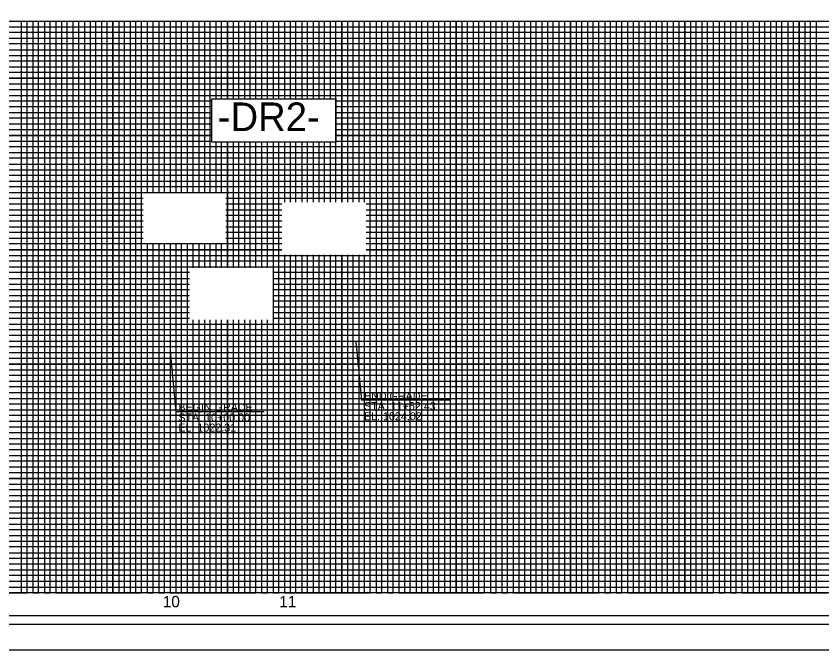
# Model space of a CAD drawing. Extents: x 1427348 to 1429459, y 856278 to 857378.
# Drawn here: x 1428179 to 1428884, y 856278 to 856832 of the extents above; entities that cross this region are included whole.
import ezdxf

# ---------------------------------------------------------------- set-up
doc = ezdxf.new("R2010")
doc.units = 0
for name, color, linetype in [('Exist Vertical Profile Horizontal Axis Label Major', 7, 'Continuous'), ('Prop Grid Mask', 7, 'Continuous'), ('Prop Vertical Profile Curve Label', 7, 'Continuous'), ('Prop VPI Label', 7, 'Continuous'), ('Sheet Cutting Line CELL', 7, 'Continuous'), ('Sheet DOT Grid CELL', 7, 'Continuous'), ('Sheet Layout Profile Border Port 2', 7, 'Continuous'), ('Sheet Plot Border Inside CELL', 7, 'Continuous'), ('Sheet Plot Border Outside CELL', 7, 'Continuous'), ('Sheet Profile CELL', 7, 'Continuous'), ('Sheet Profile Grid Major CELL', 7, 'Continuous'), ('Sheet Profile Grid Middle CELL', 7, 'Continuous'), ('Sheet Profile Grid Minor CELL', 7, 'Continuous')]:
    doc.layers.add(name, color=color, linetype=linetype)

msp = doc.modelspace()

# ---------------------------------------------------------------- linework, layer by layer
at = {"layer": 'Prop Grid Mask'}
msp.add_lwpolyline([(1428350.45, 856759.7), (1428458.77, 856759.7), (1428458.77, 856721.66), (1428350.45, 856721.66)], close=True, dxfattribs=at)
at = {"layer": 'Prop VPI Label'}
for p, q in [((1428476.42, 856547.42), (1428481.19, 856495.88)), ((1428313.99, 856538.89), (1428318.84, 856485.93)), ((1428558.65, 856495.88), (1428481.19, 856495.88)), ((1428396.3, 856485.93), (1428318.84, 856485.93))]:
    msp.add_line(p, q, dxfattribs=at)
at = {"layer": 'Sheet Cutting Line CELL'}
msp.add_line((1427596.99, 856277.58), (1429280.99, 856277.58), dxfattribs=at)
at = {"layer": 'Sheet DOT Grid CELL'}
for p, q in [((1427763.99, 856827.58), (1429263.88, 856827.58)), ((1428213.99, 856827.58), (1428213.99, 856327.58)), ((1428263.99, 856827.58), (1428263.99, 856327.58)), ((1428313.99, 856827.58), (1428313.99, 856677.37)), ((1428363.99, 856827.58), (1428363.99, 856759.7)), ((1428413.99, 856827.58), (1428413.99, 856759.7)), ((1428463.99, 856827.58), (1428463.99, 856669.07)), ((1428513.99, 856827.58), (1428513.99, 856327.58)), ((1428563.99, 856827.58), (1428563.99, 856327.58)), ((1428613.99, 856827.58), (1428613.99, 856327.58)), ((1428663.99, 856827.58), (1428663.99, 856327.58)), ((1428713.99, 856827.58), (1428713.99, 856327.58)), ((1428763.99, 856827.58), (1428763.99, 856327.58)), ((1428813.99, 856827.58), (1428813.99, 856327.58)), ((1428863.99, 856827.58), (1428863.99, 856327.58)), ((1427763.99, 856777.58), (1429263.88, 856777.58)), ((1428009.5, 856727.58), (1428350.45, 856727.58)), ((1428458.77, 856727.58), (1429263.88, 856727.58)), ((1428363.99, 856721.66), (1428363.99, 856611.64)), ((1428413.99, 856721.66), (1428413.99, 856669.07)), ((1428023.59, 856677.58), (1429263.88, 856677.58)), ((1428313.99, 856633.02), (1428313.99, 856327.58)), ((1427763.99, 856627.58), (1428411.65, 856627.58)), ((1428485.43, 856627.58), (1429263.88, 856627.58)), ((1428413.99, 856623.03), (1428413.99, 856327.58)), ((1428463.99, 856623.03), (1428463.99, 856327.58)), ((1427763.99, 856577.58), (1428330.81, 856577.58)), ((1428403.82, 856577.58), (1429263.88, 856577.58)), ((1428363.99, 856566.21), (1428363.99, 856327.58)), ((1427763.99, 856527.58), (1429263.88, 856527.58)), ((1427763.99, 856477.58), (1429263.88, 856477.58)), ((1427763.99, 856427.58), (1429263.88, 856427.58)), ((1427763.99, 856377.58), (1429263.88, 856377.58))]:
    msp.add_line(p, q, dxfattribs=at)
at = {"layer": 'Sheet Layout Profile Border Port 2'}
msp.add_lwpolyline([(1427813.99, 856827.58), (1429213.99, 856827.58), (1429213.99, 856327.58), (1427813.99, 856327.58)], close=True, dxfattribs=at)
at = {"layer": 'Sheet Plot Border Inside CELL'}
msp.add_line((1427609.99, 856300.03), (1429276.49, 856300.03), dxfattribs=at)
at = {"layer": 'Sheet Plot Border Outside CELL'}
msp.add_lwpolyline([(1427596.99, 856277.58), (1429280.99, 856277.58), (1429280.99, 857377.58), (1427596.99, 857377.58)], close=True, dxfattribs=at)
at = {"layer": 'Sheet Profile CELL'}
for p, q in [((1427763.99, 856827.58), (1429263.99, 856827.58)), ((1429263.99, 856327.58), (1427763.99, 856327.58)), ((1427763.99, 856307.58), (1429263.99, 856307.58))]:
    msp.add_line(p, q, dxfattribs=at)
msp.add_lwpolyline([(1429263.99, 857347.58), (1427763.99, 857347.58), (1427763.99, 856307.58), (1429263.99, 856307.58)], close=True, dxfattribs=at)
at = {"layer": 'Sheet Profile Grid Major CELL'}
for p, q in [((1428263.99, 856827.58), (1428313.99, 856827.58)), ((1428363.99, 856827.58), (1428413.99, 856827.58)), ((1428463.99, 856827.58), (1428513.99, 856827.58)), ((1428563.99, 856827.58), (1428613.99, 856827.58)), ((1428663.99, 856827.58), (1428713.99, 856827.58)), ((1428763.99, 856827.58), (1428813.99, 856827.58)), ((1428863.99, 856827.58), (1428913.99, 856827.58))]:
    msp.add_line(p, q, dxfattribs=at)
for points in [[(1428013.99, 856665.19), (1428013.99, 856327.58), (1428063.99, 856327.58), (1428063.99, 856827.58), (1428113.99, 856827.58), (1428113.99, 856327.58), (1428163.99, 856327.58), (1428163.99, 856827.58), (1428213.99, 856827.58), (1428213.99, 856327.58), (1428263.99, 856327.58), (1428263.99, 856827.58), (1428313.99, 856827.58), (1428313.99, 856677.37)], [(1428363.99, 856759.7), (1428363.99, 856827.58), (1428413.99, 856827.58), (1428413.99, 856759.7)], [(1428463.99, 856669.07), (1428463.99, 856827.58), (1428513.99, 856827.58), (1428513.99, 856327.58), (1428563.99, 856327.58), (1428563.99, 856827.58), (1428613.99, 856827.58), (1428613.99, 856327.58), (1428663.99, 856327.58), (1428663.99, 856827.58), (1428713.99, 856827.58), (1428713.99, 856327.58), (1428763.99, 856327.58), (1428763.99, 856827.58), (1428813.99, 856827.58), (1428813.99, 856327.58), (1428863.99, 856327.58), (1428863.99, 856827.58), (1428913.99, 856827.58)], [(1429263.99, 856777.58), (1427763.99, 856777.58)], [(1428350.45, 856727.58), (1428009.5, 856727.58)], [(1429263.99, 856727.58), (1428458.77, 856727.58)], [(1428363.99, 856611.64), (1428363.99, 856721.66)], [(1428413.99, 856721.66), (1428413.99, 856669.07)], [(1428023.59, 856677.58), (1429263.99, 856677.58)], [(1428313.99, 856633.02), (1428313.99, 856327.58), (1428363.99, 856327.58), (1428363.99, 856566.21)], [(1428411.65, 856627.58), (1427763.99, 856627.58), (1427763.99, 856577.58), (1428330.81, 856577.58)], [(1429263.99, 856627.58), (1428485.43, 856627.58)], [(1428413.99, 856623.03), (1428413.99, 856327.58), (1428463.99, 856327.58), (1428463.99, 856623.03)], [(1428403.82, 856577.58), (1429263.99, 856577.58)], [(1429263.99, 856527.58), (1427763.99, 856527.58), (1427763.99, 856477.58), (1429263.99, 856477.58)], [(1429263.99, 856427.58), (1427763.99, 856427.58), (1427763.99, 856427.58), (1427763.99, 856377.58), (1429263.99, 856377.58)], [(1429263.99, 856327.58), (1427763.99, 856327.58)]]:
    msp.add_lwpolyline(points, dxfattribs=at)
at = {"layer": 'Sheet Profile Grid Middle CELL'}
for points in [[(1427988.99, 856752.4), (1427988.99, 856827.58), (1428038.99, 856827.58), (1428038.99, 856327.58), (1428088.99, 856327.58), (1428088.99, 856827.58), (1428138.99, 856827.58), (1428138.99, 856327.58), (1428188.99, 856327.58), (1428188.99, 856827.58), (1428238.99, 856827.58), (1428238.99, 856327.58), (1428288.99, 856327.58), (1428288.99, 856827.58), (1428338.99, 856827.58), (1428338.99, 856677.37)], [(1428388.99, 856759.7), (1428388.99, 856827.58), (1428438.99, 856827.58), (1428438.99, 856759.7)], [(1428438.99, 856623.03), (1428438.99, 856327.58), (1428488.99, 856327.58), (1428488.99, 856827.58), (1428538.99, 856827.58), (1428538.99, 856327.58), (1428588.99, 856327.58), (1428588.99, 856827.58), (1428638.99, 856827.58), (1428638.99, 856327.58), (1428688.99, 856327.58), (1428688.99, 856827.58), (1428738.99, 856827.58), (1428738.99, 856327.58), (1428788.99, 856327.58), (1428788.99, 856827.58), (1428838.99, 856827.58), (1428838.99, 856327.58), (1428888.99, 856327.58)], [(1427763.99, 856802.58), (1429263.99, 856802.58)], [(1428350.45, 856752.58), (1427763.99, 856752.58), (1427763.99, 856702.58), (1427867.72, 856702.58)], [(1429263.99, 856752.58), (1428458.77, 856752.58)], [(1428388.99, 856611.64), (1428388.99, 856721.66)], [(1428438.99, 856721.66), (1428438.99, 856669.07)], [(1428023.59, 856702.58), (1429263.99, 856702.58)], [(1428290.23, 856652.58), (1427763.99, 856652.58), (1427763.99, 856602.58), (1428330.81, 856602.58)], [(1428411.65, 856652.58), (1428362.68, 856652.58)], [(1429263.99, 856652.58), (1428485.43, 856652.58)], [(1428338.99, 856633.02), (1428338.99, 856611.64)], [(1428403.82, 856602.58), (1429263.99, 856602.58)], [(1428338.99, 856566.21), (1428338.99, 856327.58), (1428388.99, 856327.58), (1428388.99, 856327.58), (1428388.99, 856566.21)], [(1429263.99, 856552.58), (1427763.99, 856552.58), (1427763.99, 856502.58), (1429263.99, 856502.58)], [(1429263.99, 856452.58), (1427763.99, 856452.58), (1427763.99, 856402.58), (1429263.99, 856402.58)], [(1429263.99, 856352.58), (1427763.99, 856352.58)]]:
    msp.add_lwpolyline(points, dxfattribs=at)
at = {"layer": 'Sheet Profile Grid Minor CELL'}
for p, q in [((1427813.99, 856822.58), (1429213.99, 856822.58)), ((1429213.99, 856817.58), (1427813.99, 856817.58)), ((1427813.99, 856812.58), (1429213.99, 856812.58)), ((1429213.99, 856807.58), (1427813.99, 856807.58)), ((1427813.99, 856797.58), (1429213.99, 856797.58)), ((1429213.99, 856792.58), (1427813.99, 856792.58)), ((1427813.99, 856787.58), (1429213.99, 856787.58)), ((1429213.99, 856782.58), (1427813.99, 856782.58)), ((1427813.99, 856772.58), (1429213.99, 856772.58)), ((1429213.99, 856767.58), (1427813.99, 856767.58)), ((1427813.99, 856762.58), (1429213.99, 856762.58)), ((1428350.45, 856757.58), (1427813.99, 856757.58)), ((1429213.99, 856757.58), (1428458.77, 856757.58)), ((1428009.5, 856747.58), (1428350.45, 856747.58)), ((1428458.77, 856747.58), (1429213.99, 856747.58)), ((1428350.45, 856742.58), (1428009.5, 856742.58)), ((1428009.5, 856737.58), (1428350.45, 856737.58)), ((1429213.99, 856742.58), (1428458.77, 856742.58)), ((1428458.77, 856737.58), (1429213.99, 856737.58)), ((1428350.45, 856732.58), (1428009.5, 856732.58)), ((1429213.99, 856732.58), (1428458.77, 856732.58)), ((1428009.5, 856722.58), (1428350.45, 856722.58)), ((1429213.99, 856717.58), (1428009.5, 856717.58)), ((1428458.77, 856722.58), (1429213.99, 856722.58)), ((1427813.99, 856712.58), (1429213.99, 856712.58)), ((1429213.99, 856707.58), (1428023.59, 856707.58)), ((1428023.59, 856697.58), (1429213.99, 856697.58)), ((1429213.99, 856692.58), (1428023.59, 856692.58)), ((1428023.59, 856687.58), (1429213.99, 856687.58)), ((1429213.99, 856682.58), (1428023.59, 856682.58)), ((1428023.59, 856672.58), (1428290.23, 856672.58)), ((1428290.23, 856667.58), (1428023.59, 856667.58)), ((1428362.68, 856672.58), (1429213.99, 856672.58)), ((1428411.65, 856667.58), (1428362.68, 856667.58)), ((1429213.99, 856667.58), (1428485.43, 856667.58)), ((1427813.99, 856662.58), (1428290.23, 856662.58)), ((1428362.68, 856662.58), (1428411.65, 856662.58)), ((1428485.43, 856662.58), (1429213.99, 856662.58)), ((1428290.23, 856657.58), (1427813.99, 856657.58)), ((1428411.65, 856657.58), (1428362.68, 856657.58)), ((1429213.99, 856657.58), (1428485.43, 856657.58)), ((1427813.99, 856647.58), (1428290.23, 856647.58)), ((1428362.68, 856647.58), (1428411.65, 856647.58)), ((1428485.43, 856647.58), (1429213.99, 856647.58)), ((1428290.23, 856642.58), (1427813.99, 856642.58)), ((1428411.65, 856642.58), (1428362.68, 856642.58)), ((1429213.99, 856642.58), (1428485.43, 856642.58)), ((1427813.99, 856637.58), (1428290.23, 856637.58)), ((1428411.65, 856632.67), (1427813.99, 856632.73)), ((1428362.68, 856637.58), (1428411.65, 856637.58)), ((1428485.43, 856637.58), (1429213.99, 856637.58)), ((1429213.99, 856632.58), (1428485.43, 856632.66)), ((1427813.99, 856622.58), (1429213.99, 856622.58)), ((1429213.99, 856617.58), (1427813.99, 856617.58)), ((1427813.99, 856612.58), (1429213.99, 856612.58)), ((1428330.81, 856607.58), (1427813.99, 856607.58)), ((1429213.99, 856607.58), (1428403.82, 856607.58)), ((1427813.99, 856597.58), (1428330.81, 856597.58)), ((1428403.82, 856597.58), (1429213.99, 856597.58)), ((1428330.81, 856592.58), (1427813.99, 856592.58)), ((1429213.99, 856592.58), (1428403.82, 856592.58)), ((1427813.99, 856587.58), (1428330.81, 856587.58)), ((1428330.81, 856582.58), (1427813.99, 856582.58)), ((1428403.82, 856587.58), (1429213.99, 856587.58)), ((1429213.99, 856582.58), (1428403.82, 856582.58)), ((1427813.99, 856572.58), (1428330.81, 856572.58)), ((1428403.82, 856572.58), (1429213.99, 856572.58)), ((1428330.81, 856567.58), (1427813.99, 856567.58)), ((1427813.99, 856562.58), (1429213.99, 856562.58)), ((1429213.99, 856567.58), (1428403.82, 856567.58)), ((1429213.99, 856557.58), (1427813.99, 856557.58)), ((1427813.99, 856547.58), (1429213.99, 856547.58)), ((1429213.99, 856542.58), (1427813.99, 856542.58)), ((1427813.99, 856537.58), (1429213.99, 856537.58)), ((1429213.99, 856532.58), (1427813.99, 856532.58)), ((1427813.99, 856522.58), (1429213.99, 856522.58)), ((1429213.99, 856517.58), (1427813.99, 856517.58)), ((1427813.99, 856512.58), (1429213.99, 856512.58)), ((1429213.99, 856507.58), (1427813.99, 856507.58)), ((1427813.99, 856497.58), (1429213.99, 856497.58)), ((1429213.99, 856492.58), (1427813.99, 856492.58)), ((1427813.99, 856487.58), (1429213.99, 856487.58)), ((1429213.99, 856482.58), (1427813.99, 856482.58)), ((1427813.99, 856472.58), (1429213.99, 856472.58)), ((1429213.99, 856467.58), (1427813.99, 856467.58)), ((1427813.99, 856462.58), (1429213.99, 856462.58)), ((1429213.99, 856457.58), (1427813.99, 856457.58)), ((1427813.99, 856447.58), (1429213.99, 856447.58)), ((1429213.99, 856442.58), (1427813.99, 856442.58)), ((1427813.99, 856437.58), (1429213.99, 856437.58)), ((1429213.99, 856432.58), (1427813.99, 856432.58)), ((1427813.99, 856422.58), (1429213.99, 856422.58)), ((1429213.99, 856417.58), (1427813.99, 856417.58)), ((1427813.99, 856412.58), (1429213.99, 856412.58)), ((1429213.99, 856407.58), (1427813.99, 856407.58)), ((1427813.99, 856397.58), (1429213.99, 856397.58)), ((1429213.99, 856392.58), (1427813.99, 856392.58)), ((1427813.99, 856387.58), (1429213.99, 856387.58)), ((1429213.99, 856382.58), (1427813.99, 856382.58)), ((1427813.99, 856372.58), (1429213.99, 856372.58)), ((1429213.99, 856367.58), (1427813.99, 856367.58)), ((1427813.99, 856362.58), (1429213.99, 856362.58)), ((1429213.99, 856357.58), (1427813.99, 856357.58)), ((1427813.99, 856347.58), (1429213.99, 856347.58)), ((1429213.99, 856342.58), (1427813.99, 856342.58)), ((1427813.99, 856337.58), (1429213.99, 856337.58)), ((1427813.99, 856332.58), (1429213.99, 856332.58))]:
    msp.add_line(p, q, dxfattribs=at)
for points in [[(1428178.99, 856327.58), (1428183.99, 856327.58), (1428183.99, 856827.58), (1428193.99, 856827.58), (1428193.99, 856327.58), (1428198.99, 856327.58), (1428198.99, 856827.58), (1428203.99, 856827.58), (1428203.99, 856327.58), (1428208.99, 856327.58), (1428208.99, 856827.58), (1428218.99, 856827.58), (1428218.99, 856327.58), (1428223.99, 856327.58), (1428223.99, 856827.58), (1428228.99, 856827.58), (1428228.99, 856327.58), (1428233.99, 856327.58), (1428233.99, 856827.58), (1428243.99, 856827.58), (1428243.99, 856327.58), (1428248.99, 856327.58), (1428248.99, 856827.58), (1428253.99, 856827.58), (1428253.99, 856327.58), (1428258.99, 856327.58), (1428258.99, 856827.58), (1428268.99, 856827.58), (1428268.99, 856327.58), (1428273.99, 856327.58), (1428273.99, 856827.58), (1428278.99, 856827.58), (1428278.99, 856327.58), (1428283.99, 856327.58), (1428283.99, 856827.58), (1428293.99, 856827.58), (1428293.99, 856677.37)], [(1428298.99, 856677.37), (1428298.99, 856827.58), (1428303.99, 856827.58), (1428303.99, 856677.37)], [(1428308.99, 856677.37), (1428308.99, 856827.58), (1428318.99, 856827.58), (1428318.99, 856677.37)], [(1428323.99, 856677.37), (1428323.99, 856827.58), (1428328.99, 856827.58), (1428328.99, 856677.37)], [(1428333.99, 856677.37), (1428333.99, 856827.58), (1428343.99, 856827.58)], [(1428343.99, 856827.58), (1428343.99, 856677.37)], [(1428348.99, 856677.37), (1428348.99, 856827.58), (1428353.99, 856827.58), (1428353.99, 856759.7)], [(1428358.99, 856759.7), (1428358.99, 856827.58), (1428368.99, 856827.58), (1428368.99, 856759.7)], [(1428373.99, 856759.7), (1428373.99, 856827.58), (1428378.99, 856827.58), (1428378.99, 856759.7)], [(1428383.99, 856759.7), (1428383.99, 856827.58), (1428393.99, 856827.58), (1428393.99, 856759.7)], [(1428398.99, 856759.7), (1428398.99, 856827.58), (1428403.99, 856827.58), (1428403.99, 856759.7)], [(1428408.99, 856759.7), (1428408.99, 856827.58), (1428418.99, 856827.58), (1428418.99, 856759.7)], [(1428423.99, 856759.7), (1428423.99, 856827.58), (1428428.99, 856827.58), (1428428.99, 856759.7)], [(1428433.99, 856759.7), (1428433.99, 856827.58), (1428443.99, 856827.58), (1428443.99, 856759.7)], [(1428448.99, 856759.7), (1428448.99, 856827.58), (1428453.99, 856827.58), (1428453.99, 856759.7)], [(1428458.99, 856669.07), (1428458.99, 856827.58), (1428468.99, 856827.58), (1428468.99, 856669.07)], [(1428473.99, 856669.07), (1428473.99, 856827.58), (1428478.99, 856827.58), (1428478.99, 856669.07)], [(1428483.99, 856669.07), (1428483.99, 856827.58), (1428493.99, 856827.58), (1428493.99, 856327.58), (1428498.99, 856327.58), (1428498.99, 856827.58), (1428503.99, 856827.58), (1428503.99, 856327.58), (1428508.99, 856327.58), (1428508.99, 856827.58), (1428518.99, 856827.58), (1428518.99, 856327.58), (1428523.99, 856327.58), (1428523.99, 856827.58), (1428528.99, 856827.58), (1428528.99, 856327.58), (1428533.99, 856327.58), (1428533.99, 856827.58), (1428543.99, 856827.58), (1428543.99, 856327.58), (1428548.99, 856327.58), (1428548.99, 856827.58), (1428553.99, 856827.58), (1428553.99, 856327.58), (1428558.99, 856327.58), (1428558.99, 856827.58), (1428568.99, 856827.58), (1428568.99, 856327.58), (1428573.99, 856327.58), (1428573.99, 856827.58), (1428578.99, 856827.58), (1428578.99, 856327.58), (1428583.99, 856327.58), (1428583.99, 856827.58), (1428593.99, 856827.58), (1428593.99, 856327.58), (1428598.99, 856327.58), (1428598.99, 856827.58), (1428603.99, 856827.58), (1428603.99, 856327.58), (1428608.99, 856327.58), (1428608.99, 856827.58), (1428618.99, 856827.58), (1428618.99, 856327.58), (1428623.69, 856328.13), (1428623.99, 856327.58), (1428623.99, 856827.58), (1428628.99, 856827.58), (1428628.99, 856327.58), (1428633.99, 856327.58), (1428633.99, 856827.58), (1428643.99, 856827.58), (1428643.99, 856327.58), (1428648.99, 856327.58)], [(1428648.99, 856327.58), (1428648.99, 856827.58), (1428653.99, 856827.58), (1428653.99, 856327.58), (1428658.99, 856327.58), (1428658.99, 856827.58), (1428668.99, 856827.58), (1428668.99, 856327.58), (1428673.99, 856327.58), (1428673.99, 856827.58), (1428678.99, 856827.58), (1428678.99, 856327.58), (1428683.99, 856327.58), (1428683.99, 856827.58), (1428693.99, 856827.58), (1428693.99, 856327.58), (1428698.99, 856327.58), (1428698.99, 856827.58), (1428703.99, 856827.58), (1428703.99, 856327.58), (1428708.99, 856327.58), (1428708.99, 856827.58), (1428718.99, 856827.58), (1428718.99, 856327.58), (1428723.99, 856327.58), (1428723.99, 856827.58), (1428728.99, 856827.58), (1428728.99, 856327.58), (1428733.99, 856327.58), (1428733.99, 856827.58), (1428743.99, 856827.58), (1428743.99, 856327.58), (1428748.99, 856327.58), (1428748.99, 856827.58), (1428753.99, 856827.58), (1428753.99, 856327.58), (1428758.99, 856327.58), (1428758.99, 856827.58), (1428768.99, 856827.58), (1428768.99, 856327.58), (1428773.99, 856327.58), (1428773.99, 856827.58), (1428778.99, 856827.58), (1428778.99, 856327.58), (1428783.99, 856327.58), (1428783.99, 856827.58), (1428793.99, 856827.58), (1428793.99, 856327.58), (1428798.99, 856327.58), (1428798.99, 856827.58), (1428803.99, 856827.58), (1428803.99, 856327.58), (1428808.99, 856327.58), (1428808.99, 856827.58), (1428818.99, 856827.58), (1428818.99, 856327.58), (1428823.99, 856327.58), (1428823.99, 856827.58), (1428828.99, 856827.58), (1428828.99, 856327.58), (1428833.99, 856327.58), (1428833.99, 856827.58), (1428843.99, 856827.58), (1428843.99, 856327.58), (1428848.99, 856327.58), (1428848.99, 856827.58), (1428853.99, 856827.58), (1428853.99, 856327.58), (1428858.99, 856327.58), (1428858.99, 856827.58), (1428868.99, 856827.58), (1428868.99, 856327.58), (1428873.99, 856327.58), (1428873.99, 856827.58), (1428878.99, 856827.58), (1428878.99, 856327.58), (1428883.99, 856327.58)], [(1428353.99, 856721.66), (1428353.99, 856677.37)], [(1428358.99, 856677.37), (1428358.99, 856721.66)], [(1428368.99, 856721.66), (1428368.99, 856611.64)], [(1428373.99, 856611.64), (1428373.99, 856721.66)], [(1428378.99, 856721.66), (1428378.99, 856611.64)], [(1428383.99, 856611.64), (1428383.99, 856721.66)], [(1428393.99, 856721.66), (1428393.99, 856611.64)], [(1428398.99, 856611.64), (1428398.99, 856721.66)], [(1428403.99, 856721.66), (1428403.99, 856327.58), (1428408.99, 856327.58), (1428408.99, 856721.66)], [(1428418.99, 856721.66), (1428418.99, 856669.07)], [(1428423.99, 856669.07), (1428423.99, 856721.66)], [(1428428.99, 856721.66), (1428428.99, 856669.07)], [(1428433.99, 856669.07), (1428433.99, 856721.66)], [(1428443.99, 856721.66), (1428443.99, 856669.07)], [(1428448.99, 856669.07), (1428448.99, 856721.66)], [(1428453.99, 856721.66), (1428453.99, 856669.07)], [(1428293.99, 856633.02), (1428293.99, 856327.58), (1428298.99, 856327.58), (1428298.99, 856633.02)], [(1428303.99, 856633.02), (1428303.99, 856327.58), (1428308.99, 856327.58), (1428308.99, 856633.02)], [(1428318.99, 856633.02), (1428318.99, 856327.58), (1428323.99, 856327.58), (1428323.99, 856633.02)], [(1428328.99, 856633.02), (1428328.99, 856327.58), (1428333.99, 856327.58), (1428333.99, 856566.21)], [(1428333.99, 856611.64), (1428333.99, 856633.02)], [(1428343.99, 856633.02), (1428343.99, 856611.64)], [(1428348.99, 856611.64), (1428348.99, 856633.02)], [(1428353.99, 856633.02), (1428353.99, 856611.64)], [(1428358.99, 856611.64), (1428358.99, 856633.02)], [(1428418.99, 856623.03), (1428418.99, 856327.58), (1428423.99, 856327.58), (1428423.99, 856623.03)], [(1428428.99, 856623.03), (1428428.99, 856327.58), (1428433.99, 856327.58), (1428433.99, 856623.03)], [(1428443.99, 856623.03), (1428443.99, 856327.58), (1428448.99, 856327.58), (1428448.99, 856623.03)], [(1428453.99, 856623.03), (1428453.99, 856327.58), (1428458.99, 856327.58), (1428458.99, 856623.03)], [(1428468.99, 856623.03), (1428468.99, 856327.58), (1428468.99, 856327.58), (1428473.99, 856327.58), (1428473.99, 856623.03)], [(1428478.99, 856623.03), (1428478.99, 856327.58), (1428483.99, 856327.58), (1428483.99, 856623.03)], [(1428343.99, 856566.21), (1428343.99, 856327.58), (1428348.99, 856327.58), (1428348.99, 856566.21)], [(1428353.99, 856566.21), (1428353.99, 856327.58), (1428358.99, 856327.58), (1428358.99, 856566.21)], [(1428368.99, 856566.21), (1428368.99, 856327.58), (1428373.99, 856327.58), (1428373.99, 856566.21)], [(1428378.99, 856566.21), (1428378.99, 856327.58), (1428383.99, 856327.58), (1428383.99, 856566.21)], [(1428393.99, 856566.21), (1428393.99, 856327.58), (1428398.99, 856327.58), (1428398.99, 856566.21)]]:
    msp.add_lwpolyline(points, dxfattribs=at)

# ---------------------------------------------------------------- texts
at = {"layer": 'Exist Vertical Profile Horizontal Axis Label Major'}
for s, p in [('10', (1428307.58, 856314.83)), ('11', (1428409.41, 856314.83))]:
    msp.add_text(s, height=10, dxfattribs=at).set_placement(p)
at = {"layer": 'Prop Vertical Profile Curve Label'}
msp.add_text('-DR2-', height=25, dxfattribs=at).set_placement((1428355.61, 856731.4))
at = {"layer": 'Prop VPI Label'}
for s, p in [('END GRADE', (1428483.49, 856496.21)), ('BEGIN GRADE', (1428321.14, 856486.27)), ('STA. 11+62.43', (1428483.49, 856487.34)), ('STA. 10+00.00', (1428321.14, 856477.39)), ('EL. 1024.02', (1428483.49, 856478.46)), ('EL. 1022.31', (1428321.14, 856468.52))]:
    msp.add_text(s, height=7, dxfattribs=at).set_placement(p)

doc.saveas('drawing.dxf')
